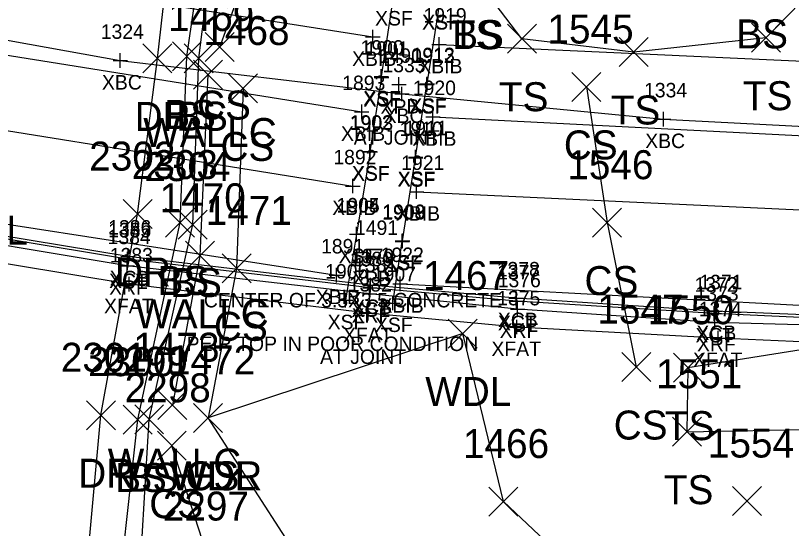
# Model space of a CAD drawing. Extents: x 1761340 to 1763889, y 696770 to 706023.
# Drawn here: x 1761657.7 to 1761711.3, y 700814.6 to 700850 of the extents above; entities that cross this region are included whole.
import ezdxf

# ---------------------------------------------------------------- set-up
doc = ezdxf.new("R2010")
doc.units = 0
for name, color, linetype in [('B_A', 7, 'Continuous'), ('B_C', 7, 'Continuous'), ('B_I', 7, 'Continuous'), ('B_TIC', 7, 'Continuous'), ('BB', 7, 'Continuous'), ('BDC', 7, 'Continuous'), ('BDEFAULT', 7, 'Continuous'), ('BELB', 7, 'Continuous'), ('BF', 7, 'Continuous'), ('BR', 7, 'Continuous'), ('L_A', 7, 'Continuous'), ('L_C', 7, 'Continuous'), ('L_I', 7, 'Continuous'), ('L_TIC', 7, 'Continuous'), ('LAWA', 7, 'Continuous'), ('LELB', 7, 'Continuous'), ('LW', 7, 'Continuous'), ('R_A', 7, 'Continuous'), ('R_I', 7, 'Continuous'), ('R_TIC', 7, 'Continuous'), ('RDP', 7, 'Continuous')]:
    doc.layers.add(name, color=color, linetype=linetype)

msp = doc.modelspace()

# ---------------------------------------------------------------- linework, layer by layer
at = {"layer": 'B_TIC'}
for p, q in [((1761682.395, 700848.561), (1761682.471, 700848.561)), ((1761686.966, 700848.05), (1761687.042, 700848.05)), ((1761664.963, 700846.932), (1761665.038, 700846.932)), ((1761682.982, 700845.839), (1761683.058, 700845.839)), ((1761682.996, 700845.76), (1761683.072, 700845.76)), ((1761684.198, 700845.275), (1761684.274, 700845.275)), ((1761686.127, 700845.269), (1761686.203, 700845.269)), ((1761686.145, 700845.32), (1761686.22, 700845.32)), ((1761684.407, 700844.626), (1761684.483, 700844.626)), ((1761681.63, 700843.391), (1761681.706, 700843.391)), ((1761686.549, 700843.049), (1761686.624, 700843.049)), ((1761702.467, 700842.89), (1761702.542, 700842.89)), ((1761682.184, 700840.657), (1761682.26, 700840.657)), ((1761682.21, 700840.63), (1761682.285, 700840.63)), ((1761685.352, 700840.22), (1761685.428, 700840.22)), ((1761685.355, 700840.274), (1761685.43, 700840.274)), ((1761681.02, 700838.268), (1761681.096, 700838.268)), ((1761685.418, 700837.88), (1761685.494, 700837.88)), ((1761681.28, 700834.951), (1761681.355, 700834.951)), ((1761681.281, 700834.942), (1761681.356, 700834.942)), ((1761684.428, 700834.453), (1761684.504, 700834.453)), ((1761684.447, 700834.498), (1761684.522, 700834.498)), ((1761665.468, 700833.226), (1761665.544, 700833.226)), ((1761665.5, 700833.418), (1761665.576, 700833.418)), ((1761682.229, 700833.394), (1761682.305, 700833.394)), ((1761665.434, 700832.762), (1761665.51, 700832.762)), ((1761679.887, 700832.117), (1761679.963, 700832.117)), ((1761665.586, 700831.495), (1761665.662, 700831.495)), ((1761682.246, 700831.437), (1761682.321, 700831.437)), ((1761684.287, 700831.525), (1761684.362, 700831.525)), ((1761682.173, 700830.837), (1761682.249, 700830.837)), ((1761682.207, 700831.236), (1761682.283, 700831.236)), ((1761680.52, 700830.383), (1761680.596, 700830.383)), ((1761692.294, 700830.53), (1761692.37, 700830.53)), ((1761692.317, 700830.32), (1761692.393, 700830.32)), ((1761683.785, 700830.194), (1761683.86, 700830.194)), ((1761692.392, 700829.783), (1761692.468, 700829.783)), ((1761682.082, 700829.49), (1761682.158, 700829.49)), ((1761705.952, 700829.474), (1761706.028, 700829.474)), ((1761705.999, 700829.643), (1761706.075, 700829.643)), ((1761706.019, 700828.859), (1761706.094, 700828.859)), ((1761692.331, 700828.536), (1761692.407, 700828.536)), ((1761706.246, 700827.778), (1761706.321, 700827.778))]:
    msp.add_line(p, q, dxfattribs=at)
for points in [[(1761682.392, 700848.061), (1761682.392, 700849.061)], [(1761681.892, 700848.561), (1761682.892, 700848.561)], [(1761686.963, 700847.55), (1761686.963, 700848.55)], [(1761686.463, 700848.05), (1761687.463, 700848.05)], [(1761664.959, 700846.432), (1761664.959, 700847.432)], [(1761664.459, 700846.932), (1761665.459, 700846.932)], [(1761682.979, 700845.339), (1761682.979, 700846.339)], [(1761682.479, 700845.839), (1761683.479, 700845.839)], [(1761682.993, 700845.26), (1761682.993, 700846.26)], [(1761686.141, 700844.82), (1761686.141, 700845.82)], [(1761682.493, 700845.76), (1761683.493, 700845.76)], [(1761683.695, 700845.275), (1761684.695, 700845.275)], [(1761684.195, 700844.775), (1761684.195, 700845.775)], [(1761685.624, 700845.269), (1761686.624, 700845.269)], [(1761685.641, 700845.32), (1761686.641, 700845.32)], [(1761686.124, 700844.769), (1761686.124, 700845.769)], [(1761684.404, 700844.126), (1761684.404, 700845.126)], [(1761683.904, 700844.626), (1761684.904, 700844.626)], [(1761681.627, 700842.891), (1761681.627, 700843.891)], [(1761681.127, 700843.391), (1761682.127, 700843.391)], [(1761686.545, 700842.549), (1761686.545, 700843.549)], [(1761702.463, 700842.39), (1761702.463, 700843.39)], [(1761686.045, 700843.049), (1761687.045, 700843.049)], [(1761701.963, 700842.89), (1761702.963, 700842.89)], [(1761682.181, 700840.157), (1761682.181, 700841.157)], [(1761682.206, 700840.13), (1761682.206, 700841.13)], [(1761681.681, 700840.657), (1761682.681, 700840.657)], [(1761681.706, 700840.63), (1761682.706, 700840.63)], [(1761685.349, 700839.72), (1761685.349, 700840.72)], [(1761685.351, 700839.774), (1761685.351, 700840.774)], [(1761684.849, 700840.22), (1761685.849, 700840.22)], [(1761684.851, 700840.274), (1761685.851, 700840.274)], [(1761681.017, 700837.768), (1761681.017, 700838.768)], [(1761685.415, 700837.38), (1761685.415, 700838.38)], [(1761680.517, 700838.268), (1761681.517, 700838.268)], [(1761684.915, 700837.88), (1761685.915, 700837.88)], [(1761681.276, 700834.451), (1761681.276, 700835.451)], [(1761681.277, 700834.442), (1761681.277, 700835.442)], [(1761680.776, 700834.951), (1761681.776, 700834.951)], [(1761680.777, 700834.942), (1761681.777, 700834.942)], [(1761684.425, 700833.953), (1761684.425, 700834.953)], [(1761684.443, 700833.998), (1761684.443, 700834.998)], [(1761683.925, 700834.453), (1761684.925, 700834.453)], [(1761683.943, 700834.498), (1761684.943, 700834.498)], [(1761665.465, 700832.726), (1761665.465, 700833.726)], [(1761665.497, 700832.918), (1761665.497, 700833.918)], [(1761682.226, 700832.894), (1761682.226, 700833.894)], [(1761664.965, 700833.226), (1761665.965, 700833.226)], [(1761664.997, 700833.418), (1761665.997, 700833.418)], [(1761665.431, 700832.262), (1761665.431, 700833.262)], [(1761681.726, 700833.394), (1761682.726, 700833.394)], [(1761664.931, 700832.762), (1761665.931, 700832.762)], [(1761679.884, 700831.617), (1761679.884, 700832.617)], [(1761665.583, 700830.995), (1761665.583, 700831.995)], [(1761679.384, 700832.117), (1761680.384, 700832.117)], [(1761682.242, 700830.937), (1761682.242, 700831.937)], [(1761684.284, 700831.025), (1761684.284, 700832.025)], [(1761665.083, 700831.495), (1761666.083, 700831.495)], [(1761681.742, 700831.437), (1761682.742, 700831.437)], [(1761682.17, 700830.337), (1761682.17, 700831.337)], [(1761682.204, 700830.736), (1761682.204, 700831.736)], [(1761683.784, 700831.525), (1761684.784, 700831.525)], [(1761680.517, 700829.883), (1761680.517, 700830.883)], [(1761681.67, 700830.837), (1761682.67, 700830.837)], [(1761681.704, 700831.236), (1761682.704, 700831.236)], [(1761692.291, 700830.03), (1761692.291, 700831.03)], [(1761692.314, 700829.82), (1761692.314, 700830.82)], [(1761680.017, 700830.383), (1761681.017, 700830.383)], [(1761683.781, 700829.694), (1761683.781, 700830.694)], [(1761691.791, 700830.53), (1761692.791, 700830.53)], [(1761691.814, 700830.32), (1761692.814, 700830.32)], [(1761692.389, 700829.283), (1761692.389, 700830.283)], [(1761682.079, 700828.99), (1761682.079, 700829.99)], [(1761683.281, 700830.194), (1761684.281, 700830.194)], [(1761691.889, 700829.783), (1761692.889, 700829.783)], [(1761705.949, 700828.974), (1761705.949, 700829.974)], [(1761705.996, 700829.143), (1761705.996, 700830.143)], [(1761681.579, 700829.49), (1761682.579, 700829.49)], [(1761705.449, 700829.474), (1761706.449, 700829.474)], [(1761705.496, 700829.643), (1761706.496, 700829.643)], [(1761706.015, 700828.359), (1761706.015, 700829.359)], [(1761692.328, 700828.036), (1761692.328, 700829.036)], [(1761705.515, 700828.859), (1761706.515, 700828.859)], [(1761691.828, 700828.536), (1761692.828, 700828.536)], [(1761706.242, 700827.278), (1761706.242, 700828.278)], [(1761705.742, 700827.778), (1761706.742, 700827.778)]]:
    msp.add_lwpolyline(points, dxfattribs=at)
at = {"layer": 'BB'}
for points in [[(1761644.371, 700854.559), (1761682.392, 700848.561)], [(1761643.757, 700849.435), (1761681.627, 700843.391)], [(1761686.963, 700848.05), (1761725.143, 700846.303)], [(1761642.912, 700844.38), (1761681.017, 700838.268)], [(1761686.545, 700843.049), (1761724.826, 700841.087)], [(1761641.817, 700837.998), (1761679.884, 700832.117)], [(1761685.415, 700837.88), (1761724.171, 700836.061)], [(1761684.284, 700831.525), (1761723.015, 700829.453)]]:
    msp.add_lwpolyline(points, dxfattribs=at)
at = {"layer": 'BDC'}
for points in [[(1761725.044, 700828.858), (1761705.996, 700829.643), (1761692.291, 700830.53), (1761682.242, 700831.437), (1761665.497, 700833.418), (1761649.588, 700836.026), (1761639.859, 700837.948), (1761622.478, 700842.11), (1761607.258, 700846.457), (1761598.593, 700849.162)], [(1761724.868, 700826.95), (1761724.871, 700828.587), (1761705.949, 700829.474), (1761692.314, 700830.32), (1761682.204, 700831.236), (1761665.465, 700833.226), (1761649.657, 700835.839), (1761639.822, 700837.803), (1761622.444, 700842.003), (1761607.253, 700846.305), (1761598.594, 700848.947), (1761598.241, 700847.438)]]:
    msp.add_lwpolyline(points, dxfattribs=at)
at = {"layer": 'BDEFAULT'}
for points in [[(1761685.225, 700860.586), (1761684.474, 700856.102), (1761683.792, 700851.352), (1761682.979, 700845.839), (1761682.993, 700845.76), (1761682.181, 700840.657), (1761682.206, 700840.63), (1761681.276, 700834.951), (1761681.277, 700834.942), (1761680.517, 700830.383)], [(1761683.781, 700830.194), (1761684.425, 700834.453), (1761684.443, 700834.498), (1761685.349, 700840.22), (1761685.351, 700840.274), (1761686.124, 700845.269), (1761686.141, 700845.32), (1761687.043, 700851.073), (1761687.049, 700851.093), (1761688.593, 700860.614)]]:
    msp.add_lwpolyline(points, dxfattribs=at)
at = {"layer": 'BELB'}
msp.add_lwpolyline([(1761601.149, 700861.879), (1761622.312, 700855.499), (1761642.198, 700851.032), (1761664.959, 700846.932), (1761684.404, 700844.626), (1761702.463, 700842.89), (1761719.736, 700841.994), (1761727.361, 700840.892)], dxfattribs=at)
at = {"layer": 'BF'}
msp.add_lwpolyline([(1761724.868, 700826.95), (1761706.242, 700827.778), (1761692.328, 700828.536), (1761682.079, 700829.49), (1761665.583, 700831.495), (1761649.292, 700834.2), (1761639.519, 700836.163), (1761621.811, 700840.338), (1761606.756, 700844.682), (1761598.241, 700847.438)], dxfattribs=at)
at = {"layer": 'BR'}
msp.add_lwpolyline([(1761724.372, 700828.339), (1761706.015, 700828.859), (1761692.389, 700829.783), (1761682.17, 700830.837), (1761665.431, 700832.762), (1761649.683, 700835.39), (1761639.866, 700837.475), (1761622.504, 700841.455), (1761607.196, 700845.805), (1761599.069, 700848.455)], dxfattribs=at)
at = {"layer": 'L_TIC'}
for points in [[(1761691.689, 700847.437), (1761693.689, 700849.437)], [(1761693.689, 700847.437), (1761691.689, 700849.437)], [(1761708.534, 700847.506), (1761710.534, 700849.506)], [(1761710.534, 700847.506), (1761708.534, 700849.506)], [(1761670.82, 700846.861), (1761672.82, 700848.861)], [(1761672.82, 700846.861), (1761670.82, 700848.861)], [(1761699.41, 700846.52), (1761701.41, 700848.52)], [(1761701.41, 700846.52), (1761699.41, 700848.52)], [(1761668.554, 700846.216), (1761670.554, 700848.216)], [(1761670.554, 700846.216), (1761668.554, 700848.216)], [(1761669.376, 700846.091), (1761671.376, 700848.091)], [(1761671.376, 700846.091), (1761669.376, 700848.091)], [(1761670.01, 700844.965), (1761672.01, 700846.965)], [(1761672.01, 700844.965), (1761670.01, 700846.965)], [(1761672.434, 700844.006), (1761674.434, 700846.006)], [(1761674.434, 700844.006), (1761672.434, 700846.006)], [(1761696.14, 700844.109), (1761698.14, 700846.109)], [(1761698.14, 700844.109), (1761696.14, 700846.109)], [(1761668.086, 700834.752), (1761670.086, 700836.752)], [(1761670.086, 700834.752), (1761668.086, 700836.752)], [(1761697.566, 700834.744), (1761699.566, 700836.744)], [(1761699.566, 700834.744), (1761697.566, 700836.744)], [(1761668.965, 700834.611), (1761670.965, 700836.611)], [(1761670.965, 700834.611), (1761668.965, 700836.611)], [(1761669.455, 700832.46), (1761671.455, 700834.46)], [(1761671.455, 700832.46), (1761669.455, 700834.46)], [(1761671.985, 700831.588), (1761673.985, 700833.588)], [(1761673.985, 700831.588), (1761671.985, 700833.588)], [(1761687.596, 700827.091), (1761689.596, 700829.091)], [(1761689.596, 700827.091), (1761687.596, 700829.091)], [(1761699.584, 700824.773), (1761701.584, 700826.773)], [(1761701.584, 700824.773), (1761699.584, 700826.773)], [(1761703.151, 700824.73), (1761705.151, 700826.73)], [(1761705.151, 700824.73), (1761703.151, 700826.73)], [(1761667.555, 700822.146), (1761669.555, 700824.146)], [(1761669.555, 700822.146), (1761667.555, 700824.146)], [(1761665.165, 700821.147), (1761667.165, 700823.147)], [(1761667.165, 700821.147), (1761665.165, 700823.147)], [(1761665.952, 700821.175), (1761667.952, 700823.175)], [(1761667.952, 700821.175), (1761665.952, 700823.175)], [(1761670.016, 700821.268), (1761672.016, 700823.268)], [(1761672.016, 700821.268), (1761670.016, 700823.268)], [(1761670.016, 700821.268), (1761672.016, 700823.268)], [(1761672.016, 700821.268), (1761670.016, 700823.268)], [(1761670.016, 700821.268), (1761672.016, 700823.268)], [(1761672.016, 700821.268), (1761670.016, 700823.268)], [(1761703.076, 700820.31), (1761705.076, 700822.31)], [(1761705.076, 700820.31), (1761703.076, 700822.31)], [(1761667.518, 700819.344), (1761669.518, 700821.344)], [(1761669.518, 700819.344), (1761667.518, 700821.344)], [(1761690.412, 700815.494), (1761692.412, 700817.494)], [(1761692.412, 700815.494), (1761690.412, 700817.494)], [(1761707.216, 700815.531), (1761709.216, 700817.531)], [(1761709.216, 700815.531), (1761707.216, 700817.531)]]:
    msp.add_lwpolyline(points, dxfattribs=at)
at = {"layer": 'LAWA'}
for points in [[(1761700.836, 700775.672), (1761698.742, 700791.327), (1761699.629, 700808.733), (1761691.412, 700816.494), (1761688.596, 700828.091), (1761671.016, 700822.268)], [(1761671.881, 700734.037), (1761671.547, 700759.08), (1761673.579, 700793.066), (1761679.613, 700808.977), (1761671.016, 700822.268)]]:
    msp.add_lwpolyline(points, dxfattribs=at)
at = {"layer": 'LELB'}
for points in [[(1761681.301, 700585.517), (1761671.929, 700613.506), (1761667.591, 700648.271), (1761662.956, 700684.404), (1761660.968, 700720.859), (1761660.494, 700762.081), (1761662.811, 700791.593), (1761666.165, 700822.147), (1761669.086, 700835.752), (1761669.554, 700847.216), (1761671.381, 700859.702), (1761679.654, 700896.376), (1761688.232, 700933.044), (1761696.404, 700960.959), (1761706.351, 700997.906), (1761723.358, 701026.155)], [(1761684.453, 700586.471), (1761674.154, 700613.84), (1761669.556, 700648.243), (1761665.944, 700684.581), (1761663.689, 700720.734), (1761662.667, 700762.265), (1761665.109, 700791.249), (1761666.952, 700822.175), (1761669.965, 700835.611), (1761670.376, 700847.091), (1761671.954, 700859.509), (1761680.672, 700895.811), (1761689.739, 700932.613), (1761697.717, 700961.083), (1761707.94, 700997.332), (1761724.654, 701022.108)], [(1761671.82, 700847.861), (1761675.695, 700858.554), (1761680.099, 700876.066)], [(1761687.875, 700863.195), (1761712.355, 700861.111), (1761714.798, 700853.885), (1761709.534, 700848.506), (1761700.41, 700847.52), (1761692.689, 700848.437), (1761689.436, 700852.719)], [(1761673.434, 700845.006), (1761672.985, 700832.588), (1761671.016, 700822.268)], [(1761697.14, 700845.109), (1761698.566, 700835.744), (1761700.584, 700825.773)], [(1761723.41, 700828.779), (1761704.151, 700825.73), (1761704.076, 700821.31), (1761722.344, 700821.669), (1761739.398, 700821.555)], [(1761685.098, 700588.241), (1761679.12, 700609.905), (1761673.288, 700649.096), (1761669.603, 700684.443), (1761667.581, 700720.712), (1761666.679, 700761.335), (1761668.826, 700791.969), (1761671.153, 700812.18), (1761668.518, 700820.344)]]:
    msp.add_lwpolyline(points, dxfattribs=at)
at = {"layer": 'LW'}
msp.add_lwpolyline([(1761671.01, 700845.965), (1761670.455, 700833.46), (1761668.555, 700823.146)], dxfattribs=at)
at = {"layer": 'R_TIC'}
for points in [[(1761666.517, 700846.08), (1761668.517, 700848.08)], [(1761668.517, 700846.08), (1761666.517, 700848.08)], [(1761665.152, 700835.338), (1761667.152, 700837.338)], [(1761667.152, 700835.338), (1761665.152, 700837.338)], [(1761662.623, 700821.45), (1761664.623, 700823.45)], [(1761664.623, 700821.45), (1761662.623, 700823.45)]]:
    msp.add_lwpolyline(points, dxfattribs=at)
at = {"layer": 'RDP'}
msp.add_lwpolyline([(1761685.903, 700541.843), (1761678.398, 700578.094), (1761669.593, 700613.166), (1761665.81, 700647.626), (1761660.309, 700684.319), (1761659.551, 700721.027), (1761658.733, 700762.092), (1761660.802, 700791.687), (1761663.623, 700822.45), (1761666.152, 700836.338), (1761667.517, 700847.08), (1761668.947, 700859.679), (1761676.875, 700896.799), (1761686.16, 700933.202), (1761693.935, 700961.975), (1761704.585, 700998.319), (1761705.06, 700999.037), (1761715.839, 701034.881), (1761727.081, 701077.741), (1761742.289, 701129.681)], dxfattribs=at)

# ---------------------------------------------------------------- texts
at = {"layer": 'B_A'}
for s, p in [('XSF', (1761682.552, 700849.352)), ('XSF', (1761685.803, 700849.073)), ('XSF', (1761685.809, 700849.093)), ('XBIB', (1761680.963, 700846.561)), ('XBIB', (1761685.534, 700846.05)), ('XBC', (1761663.695, 700844.932)), ('XSF', (1761681.739, 700843.839)), ('XSF', (1761681.753, 700843.76)), ('XPB', (1761682.931, 700843.275)), ('XSF', (1761684.884, 700843.269)), ('XSF', (1761684.901, 700843.32)), ('XBC', (1761683.14, 700842.626)), ('XBIB', (1761680.197, 700841.391)), ('XBIB', (1761685.116, 700841.049)), ('XBC', (1761701.2, 700840.89)), ('XSF', (1761680.941, 700838.657)), ('XSF', (1761680.966, 700838.63)), ('XSF', (1761684.109, 700838.22)), ('XSF', (1761684.111, 700838.274)), ('XBIB', (1761679.588, 700836.268)), ('XBIB', (1761683.986, 700835.88)), ('XSF', (1761680.036, 700832.951)), ('XSF', (1761680.037, 700832.942)), ('XSF', (1761683.203, 700832.498)), ('XSF', (1761683.184, 700832.453)), ('XCB', (1761664.233, 700831.418)), ('XCT', (1761664.185, 700831.226)), ('XPB', (1761680.962, 700831.394)), ('XRF', (1761664.191, 700830.762)), ('XBIB', (1761678.455, 700830.117)), ('XFAT', (1761663.839, 700829.495)), ('XCB', (1761680.978, 700829.437)), ('XBIB', (1761682.854, 700829.525)), ('XCT', (1761680.924, 700829.236)), ('XRF', (1761680.93, 700828.837)), ('XSF', (1761679.277, 700828.383)), ('XSF', (1761682.541, 700828.194)), ('XCB', (1761691.027, 700828.53)), ('XCT', (1761691.034, 700828.32)), ('XRF', (1761691.149, 700827.783)), ('XCB', (1761704.732, 700827.643)), ('XFAT', (1761680.335, 700827.49)), ('XCT', (1761704.669, 700827.474)), ('XRF', (1761704.775, 700826.859)), ('XFAT', (1761690.584, 700826.536)), ('XFAT', (1761704.498, 700825.778))]:
    msp.add_text(s, height=1, dxfattribs=at).set_placement(p)
at = {"layer": 'B_C'}
for s, p in [('AT JOINT', (1761681.077, 700841.126)), ('CENTER OF 3.5X3.5 CONCRETE', (1761670.73, 700829.894)), ('PEIR TOP IN POOR CONDITION', (1761669.537, 700826.883)), ('AT JOINT', (1761678.752, 700825.99))]:
    msp.add_text(s, height=1, dxfattribs=at).set_placement(p)
at = {"layer": 'B_I'}
for s, p in [('1919', (1761685.896, 700849.55)), ('1324', (1761663.613, 700848.432)), ('1900', (1761681.55, 700847.339)), ('1901', (1761681.891, 700847.26)), ('1490', (1761682.805, 700846.775)), ('1912', (1761685.061, 700846.769)), ('1913', (1761685.078, 700846.82)), ('1333', (1761683.057, 700846.126)), ('1893', (1761680.28, 700844.891)), ('1920', (1761685.156, 700844.549)), ('1334', (1761701.117, 700844.39)), ('1902', (1761680.795, 700842.157)), ('1903', (1761680.821, 700842.13)), ('1910', (1761684.243, 700841.72)), ('1911', (1761684.572, 700841.774)), ('1892', (1761679.67, 700839.768)), ('1921', (1761684.352, 700839.38)), ('1904', (1761679.89, 700836.451)), ('1905', (1761679.891, 700836.442)), ('1908', (1761683.039, 700835.953)), ('1909', (1761683.054, 700835.998)), ('1385', (1761664.119, 700834.726)), ('1386', (1761664.123, 700834.918)), ('1491', (1761681.163, 700834.894)), ('1384', (1761664.085, 700834.262)), ('1891', (1761678.821, 700833.617)), ('1383', (1761664.236, 700832.995)), ('1922', (1761682.937, 700833.025)), ('1380', (1761680.814, 700832.736)), ('1379', (1761680.892, 700832.937)), ('1381', (1761681.107, 700832.337)), ('1378', (1761690.944, 700832.03)), ('1906', (1761679.103, 700831.883)), ('1907', (1761682.396, 700831.694)), ('1377', (1761690.968, 700831.82)), ('1382', (1761680.732, 700830.99)), ('1376', (1761691.015, 700831.283)), ('1372', (1761704.602, 700830.974)), ('1371', (1761704.933, 700831.143)), ('1373', (1761704.669, 700830.359)), ('1375', (1761690.981, 700830.036)), ('1374', (1761704.896, 700829.278))]:
    msp.add_text(s, height=1, dxfattribs=at).set_placement(p)
at = {"layer": 'L_A'}
for s, p in [('TS', (1761687.845, 700847.719)), ('BS', (1761687.877, 700847.719)), ('BS', (1761707.487, 700847.771)), ('TS', (1761691.098, 700843.437)), ('TS', (1761707.943, 700843.506)), ('CS', (1761670.261, 700842.861)), ('BS', (1761667.995, 700842.216)), ('TS', (1761698.82, 700842.52)), ('BS', (1761668.817, 700842.091)), ('WALLC', (1761666.546, 700840.965)), ('CS', (1761695.581, 700840.109)), ('CS', (1761671.875, 700840.006)), ('BS', (1761667.527, 700830.752)), ('BS', (1761668.406, 700830.611)), ('CS', (1761697.007, 700830.744)), ('WALLC', (1761665.99, 700828.46)), ('CS', (1761671.426, 700827.588)), ('WDL', (1761686.013, 700823.091)), ('CS', (1761699.025, 700820.773)), ('TS', (1761702.56, 700820.73)), ('WALLC', (1761664.091, 700818.146)), ('BS', (1761664.606, 700817.147)), ('BS', (1761665.393, 700817.175)), ('WDR', (1761668.378, 700817.268)), ('WDL', (1761668.434, 700817.268)), ('CS', (1761669.457, 700817.268)), ('TS', (1761702.486, 700816.31)), ('CS', (1761666.959, 700815.344))]:
    msp.add_text(s, height=2, dxfattribs=at).set_placement(p)
at = {"layer": 'L_C'}
msp.add_text('RETAINING WALL MADE OF STEEL', height=2, dxfattribs=at).set_placement((1761613.851, 700834.229))
at = {"layer": 'L_I'}
for s, p in [('1469', (1761668.262, 700848.965)), ('1545', (1761694.448, 700848.109)), ('1468', (1761670.694, 700848.006)), ('2303', (1761665.747, 700838.752)), ('2304', (1761666.627, 700838.611)), ('1546', (1761695.818, 700838.744)), ('1470', (1761667.675, 700836.46)), ('1471', (1761670.859, 700835.588)), ('1467', (1761685.856, 700831.091)), ('1547', (1761697.891, 700828.773)), ('1550', (1761701.372, 700828.73)), ('1473', (1761665.862, 700826.146)), ('2300', (1761662.74, 700825.147)), ('2299', (1761663.684, 700825.175)), ('1472', (1761668.324, 700825.268)), ('1472', (1761668.324, 700825.268)), ('1472', (1761668.324, 700825.268)), ('1551', (1761701.95, 700824.31)), ('2298', (1761665.258, 700823.344)), ('1466', (1761688.617, 700819.494)), ('1554', (1761705.524, 700819.531)), ('2297', (1761667.893, 700815.18))]:
    msp.add_text(s, height=2, dxfattribs=at).set_placement(p)
at = {"layer": 'R_A'}
for p in [(1761665.951, 700842.08), (1761664.585, 700831.338), (1761662.056, 700817.45)]:
    msp.add_text('DR', height=2, dxfattribs=at).set_placement(p)
at = {"layer": 'R_I'}
for s, p in [('2302', (1761662.814, 700839.338)), ('2301', (1761660.852, 700825.45))]:
    msp.add_text(s, height=2, dxfattribs=at).set_placement(p)

doc.saveas('drawing.dxf')
